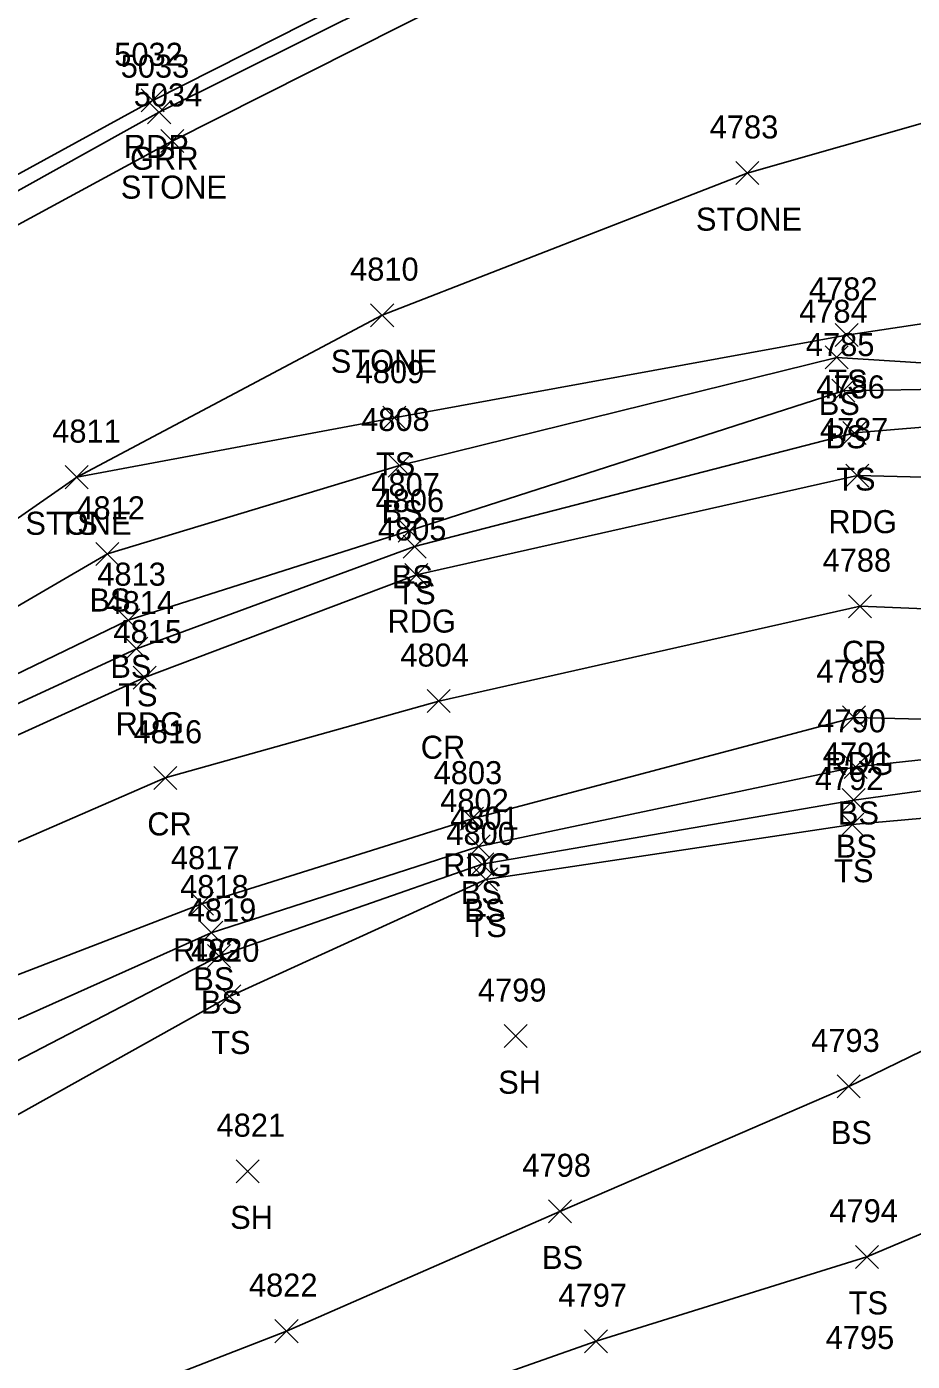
# Model space of a CAD drawing. Extents: x 1505656 to 1508446, y 700805 to 703031.
# Drawn here: x 1506352.2 to 1506429, y 701620.6 to 701736.4 of the extents above; entities that cross this region are included whole.
import ezdxf

# ---------------------------------------------------------------- set-up
doc = ezdxf.new("R2010")
doc.units = 0
for name, color, linetype in [('L_A', 7, 'Continuous'), ('L_I', 7, 'Continuous'), ('L_TIC', 7, 'Continuous'), ('LASF', 7, 'Continuous'), ('LELB', 7, 'Continuous'), ('P_A', 7, 'Continuous'), ('P_I', 7, 'Continuous'), ('P_TIC', 7, 'Continuous'), ('PET', 7, 'Continuous'), ('PEU', 7, 'Continuous'), ('PRC', 7, 'Continuous'), ('R_A', 7, 'Continuous'), ('R_I', 7, 'Continuous'), ('R_TIC', 7, 'Continuous'), ('RGR', 7, 'Continuous')]:
    doc.layers.add(name, color=color, linetype=linetype)

msp = doc.modelspace()

# ---------------------------------------------------------------- linework, layer by layer
at = {"layer": 'L_TIC'}
for points in [[(1506363.79, 701725.48), (1506365.79, 701727.48)], [(1506365.79, 701725.48), (1506363.79, 701727.48)], [(1506413.7, 701722.7), (1506415.7, 701724.7)], [(1506415.7, 701722.7), (1506413.7, 701724.7)], [(1506382.01, 701710.36), (1506384.01, 701712.36)], [(1506384.01, 701710.36), (1506382.01, 701712.36)], [(1506422.31, 701708.64), (1506424.31, 701710.64)], [(1506424.31, 701708.64), (1506422.31, 701710.64)], [(1506421.46, 701706.7), (1506423.46, 701708.7)], [(1506423.46, 701706.7), (1506421.46, 701708.7)], [(1506422.04, 701703.81), (1506424.04, 701705.81)], [(1506424.04, 701703.81), (1506422.04, 701705.81)], [(1506383.06, 701701.46), (1506385.06, 701703.46)], [(1506385.06, 701701.46), (1506383.06, 701703.46)], [(1506423, 701700.14), (1506425, 701702.14)], [(1506425, 701700.14), (1506423, 701702.14)], [(1506383.52, 701697.31), (1506385.52, 701699.31)], [(1506385.52, 701697.31), (1506383.52, 701699.31)], [(1506355.51, 701696.3), (1506357.51, 701698.3)], [(1506357.51, 701696.3), (1506355.51, 701698.3)], [(1506355.51, 701696.3), (1506357.51, 701698.3)], [(1506357.51, 701696.3), (1506355.51, 701698.3)], [(1506384.41, 701691.66), (1506386.41, 701693.66)], [(1506386.41, 701691.66), (1506384.41, 701693.66)], [(1506384.83, 701690.27), (1506386.83, 701692.27)], [(1506386.83, 701690.27), (1506384.83, 701692.27)], [(1506358.17, 701689.64), (1506360.17, 701691.64)], [(1506360.17, 701689.64), (1506358.17, 701691.64)], [(1506359.98, 701683.88), (1506361.98, 701685.88)], [(1506361.98, 701683.88), (1506359.98, 701685.88)], [(1506360.69, 701681.41), (1506362.69, 701683.41)], [(1506362.69, 701681.41), (1506360.69, 701683.41)], [(1506423.11, 701671.15), (1506425.11, 701673.15)], [(1506425.11, 701671.15), (1506423.11, 701673.15)], [(1506422.94, 701668.27), (1506424.94, 701670.27)], [(1506424.94, 701668.27), (1506422.94, 701670.27)], [(1506422.82, 701666.14), (1506424.82, 701668.14)], [(1506424.82, 701666.14), (1506422.82, 701668.14)], [(1506390.39, 701664.24), (1506392.39, 701666.24)], [(1506392.39, 701664.24), (1506390.39, 701666.24)], [(1506390.69, 701662.7), (1506392.69, 701664.7)], [(1506392.69, 701662.7), (1506390.69, 701664.7)], [(1506391.01, 701661.38), (1506393.01, 701663.38)], [(1506393.01, 701661.38), (1506391.01, 701663.38)], [(1506367.18, 701656.76), (1506369.18, 701658.76)], [(1506369.18, 701656.76), (1506367.18, 701658.76)], [(1506367.84, 701654.73), (1506369.84, 701656.73)], [(1506369.84, 701654.73), (1506367.84, 701656.73)], [(1506368.76, 701651.23), (1506370.76, 701653.23)], [(1506370.76, 701651.23), (1506368.76, 701653.23)], [(1506393.59, 701647.78), (1506395.59, 701649.78)], [(1506395.59, 701647.78), (1506393.59, 701649.78)], [(1506422.5, 701643.41), (1506424.5, 701645.41)], [(1506424.5, 701643.41), (1506422.5, 701645.41)], [(1506370.34, 701636.05), (1506372.34, 701638.05)], [(1506372.34, 701636.05), (1506370.34, 701638.05)], [(1506397.44, 701632.57), (1506399.44, 701634.57)], [(1506399.44, 701632.57), (1506397.44, 701634.57)], [(1506424.08, 701628.62), (1506426.08, 701630.62)], [(1506426.08, 701628.62), (1506424.08, 701630.62)], [(1506373.71, 701622.17), (1506375.71, 701624.17)], [(1506375.71, 701622.17), (1506373.71, 701624.17)], [(1506400.57, 701621.29), (1506402.57, 701623.29)], [(1506402.57, 701621.29), (1506400.57, 701623.29)]]:
    msp.add_lwpolyline(points, dxfattribs=at)
at = {"layer": 'LASF'}
msp.add_lwpolyline([(1506429.68, 701752.83), (1506443.79, 701749.58), (1506462.7, 701738.25), (1506448, 701734.79), (1506439.12, 701730.66), (1506414.7, 701723.7), (1506383.01, 701711.36), (1506356.51, 701697.3), (1506322.23, 701673.42), (1506294.03, 701680.48), (1506288.73, 701684.49), (1506312.05, 701697.87), (1506364.79, 701726.48), (1506396.56, 701742.51), (1506417.45, 701749.86)], dxfattribs=at)
at = {"layer": 'LELB'}
for points in [[(1506444.2, 701712.77), (1506423.31, 701709.64), (1506384.06, 701702.46), (1506356.51, 701697.3)], [(1506439.67, 701705.09), (1506439.84, 701706.59), (1506422.46, 701707.7), (1506384.52, 701698.31), (1506359.17, 701690.64), (1506320.25, 701667.95), (1506278.54, 701648.54), (1506245.9, 701631.84)], [(1506439.67, 701705.09), (1506423.04, 701704.81), (1506385.41, 701692.66), (1506360.98, 701684.88), (1506321.19, 701665.64), (1506279.84, 701646.54), (1506249.51, 701629.08), (1506209.1, 701611.11), (1506171.89, 701595.41), (1506131.01, 701577.86), (1506104.62, 701564.81), (1506102.86, 701567.32), (1506129.39, 701579.69), (1506163.08, 701601.74)], [(1506443.16, 701702.73), (1506424, 701701.14), (1506385.83, 701691.27), (1506361.69, 701682.41), (1506322.45, 701664.3), (1506280.69, 701644.91), (1506249.51, 701629.08)], [(1506509.21, 701611.03), (1506507.44, 701618.38), (1506501.19, 701629.63), (1506493.28, 701641.73), (1506487.58, 701650), (1506474.34, 701662.65), (1506459.98, 701669.04), (1506440.83, 701673.95), (1506424.11, 701672.15), (1506391.39, 701665.24), (1506368.18, 701657.76), (1506332.08, 701641.61), (1506290.37, 701623.5), (1506260.15, 701608.32), (1506217.93, 701589.2), (1506179.42, 701572.42), (1506142.47, 701555.66), (1506111.55, 701540.68), (1506083.73, 701530.64), (1506052.54, 701524.58), (1506019.1, 701514.86), (1506001, 701512.92)], [(1506505.93, 701609.05), (1506503.05, 701618.08), (1506498.28, 701627.09), (1506492.11, 701640.81), (1506486.47, 701649.13), (1506473.24, 701661.34), (1506459.24, 701667.42), (1506439.7, 701671.42), (1506423.94, 701669.27), (1506391.69, 701663.7), (1506368.84, 701655.73), (1506334.29, 701637.81), (1506294.64, 701613.24), (1506262.7, 701600.99), (1506219.1, 701587.01), (1506179.81, 701571.09), (1506142.47, 701555.66)], [(1506501.04, 701604.88), (1506496.49, 701618.92), (1506488.49, 701638.33), (1506484.16, 701646.68), (1506470.49, 701657.41), (1506458.02, 701664.05), (1506439.08, 701668.51), (1506423.82, 701667.14), (1506392.01, 701662.38), (1506369.76, 701652.23), (1506335.43, 701633.06), (1506298.71, 701603.99)], [(1506477.45, 701634.17), (1506465.86, 701646.11), (1506449.94, 701651.79), (1506436.18, 701650.58), (1506423.5, 701644.41), (1506398.44, 701633.57), (1506374.71, 701623.17), (1506339.34, 701609.43), (1506298.71, 701603.99), (1506265.2, 701595.37), (1506220.27, 701580.75), (1506181.48, 701566.74)], [(1506464.89, 701630.33), (1506459.78, 701641.23), (1506438.81, 701635.44), (1506425.08, 701629.62), (1506401.57, 701622.29), (1506377.12, 701613.69), (1506342.27, 701601.76), (1506302.18, 701594.41), (1506270.03, 701583.3), (1506223.11, 701570.14), (1506184.48, 701557.95), (1506143.89, 701547.39), (1506113.07, 701537.26)]]:
    msp.add_lwpolyline(points, dxfattribs=at)
at = {"layer": 'P_TIC'}
for points in [[(1506362.1, 701729.01), (1506364.1, 701731.01)], [(1506364.1, 701729.01), (1506362.1, 701731.01)], [(1506423.25, 701696.44), (1506425.25, 701698.44)], [(1506425.25, 701696.44), (1506423.25, 701698.44)], [(1506384.98, 701687.81), (1506386.98, 701689.81)], [(1506386.98, 701687.81), (1506384.98, 701689.81)], [(1506423.49, 701685.1), (1506425.49, 701687.1)], [(1506425.49, 701685.1), (1506423.49, 701687.1)], [(1506361.39, 701678.9), (1506363.39, 701680.9)], [(1506363.39, 701678.9), (1506361.39, 701680.9)], [(1506386.92, 701676.86), (1506388.92, 701678.86)], [(1506388.92, 701676.86), (1506386.92, 701678.86)], [(1506422.96, 701675.45), (1506424.96, 701677.45)], [(1506424.96, 701675.45), (1506422.96, 701677.45)], [(1506363.19, 701670.2), (1506365.19, 701672.2)], [(1506365.19, 701670.2), (1506363.19, 701672.2)], [(1506389.82, 701666.65), (1506391.82, 701668.65)], [(1506391.82, 701666.65), (1506389.82, 701668.65)], [(1506366.37, 701659.27), (1506368.37, 701661.27)], [(1506368.37, 701659.27), (1506366.37, 701661.27)]]:
    msp.add_lwpolyline(points, dxfattribs=at)
at = {"layer": 'PET'}
msp.add_lwpolyline([(1505992.82, 701526.62), (1506019.68, 701536.96), (1506041.12, 701547.38), (1506078.94, 701568.61), (1506107.14, 701585.72), (1506155.42, 701613.4), (1506197.61, 701637.13), (1506235.98, 701659.24), (1506270.79, 701679.06), (1506309.7, 701700.77), (1506363.1, 701730.01), (1506394.98, 701746.14), (1506415.62, 701755.89), (1506435.04, 701763.8), (1506427.31, 701775.57), (1506419.65, 701788)], dxfattribs=at)
at = {"layer": 'PEU'}
for points in [[(1506525.78, 701615.67), (1506519.5, 701633.43), (1506513.15, 701649.3), (1506503.08, 701665.91), (1506489.52, 701679.31), (1506470.51, 701690.89), (1506460.49, 701693.33), (1506439.12, 701697.08), (1506424.25, 701697.44), (1506385.98, 701688.81), (1506362.39, 701679.9), (1506323.43, 701662.22), (1506281.23, 701643.19), (1506252.35, 701627.76), (1506209.85, 701609.53), (1506173.44, 701590.33), (1506132.93, 701573.39), (1506105.98, 701559.11), (1506089.21, 701557.37), (1506082.67, 701561.4), (1506078.94, 701568.61)], [(1506512.36, 701612.05), (1506509.58, 701619.24), (1506503.6, 701631.14), (1506495.87, 701643.5), (1506490.15, 701651.91), (1506475.68, 701664.25), (1506461.93, 701671.49), (1506441.69, 701676.01), (1506423.96, 701676.45), (1506390.82, 701667.65), (1506367.37, 701660.27), (1506329.82, 701645.8), (1506288.78, 701627.12), (1506258.45, 701612.59), (1506216.06, 701594.6), (1506177.68, 701577.39), (1506139.98, 701558.64), (1506110.2, 701544.77), (1506096.87, 701538.26), (1506082.45, 701533.62), (1506051.95, 701526.91), (1506019.21, 701522.3), (1505992.82, 701526.62)]]:
    msp.add_lwpolyline(points, dxfattribs=at)
at = {"layer": 'PRC'}
msp.add_lwpolyline([(1506519.07, 701614.01), (1506506.17, 701642.82), (1506497.05, 701654.53), (1506481.68, 701671.51), (1506464.91, 701680.72), (1506446.99, 701685.19), (1506424.49, 701686.1), (1506387.92, 701677.86), (1506364.19, 701671.2), (1506326.34, 701654.75), (1506285.02, 701635.25), (1506254.86, 701621.58), (1506213.39, 701600.27), (1506174.81, 701583.72), (1506136.29, 701565.39), (1506108.2, 701552.45), (1506085.49, 701543.92), (1506066.01, 701541.94)], dxfattribs=at)
at = {"layer": 'R_TIC'}
for points in [[(1506362.66, 701727.98), (1506364.66, 701729.98)], [(1506364.66, 701727.98), (1506362.66, 701729.98)]]:
    msp.add_lwpolyline(points, dxfattribs=at)
at = {"layer": 'RGR'}
msp.add_lwpolyline([(1506085.73, 701568.29), (1506107.54, 701584.72), (1506155.8, 701612.35), (1506198.2, 701636.56), (1506236.66, 701658.36), (1506270.99, 701677.92), (1506310.51, 701699.4), (1506363.66, 701728.98), (1506395.74, 701744.99), (1506415.68, 701754.26), (1506427.01, 701758.86)], dxfattribs=at)

# ---------------------------------------------------------------- texts
at = {"layer": 'L_A'}
for s, p in [('STONE', (1506360.33, 701721.48)), ('STONE', (1506410.24, 701718.7)), ('STONE', (1506378.55, 701706.36)), ('TS', (1506421.72, 701704.64)), ('BS', (1506420.9, 701702.7)), ('BS', (1506421.48, 701699.81)), ('TS', (1506382.47, 701697.46)), ('TS', (1506422.41, 701696.14)), ('STONE', (1506352.05, 701692.3)), ('TS', (1506354.92, 701692.3)), ('BS', (1506382.96, 701693.31)), ('BS', (1506383.85, 701687.66)), ('BS', (1506357.61, 701685.64)), ('TS', (1506384.24, 701686.27)), ('BS', (1506359.42, 701679.88)), ('TS', (1506360.1, 701677.41)), ('BS', (1506422.56, 701667.15)), ('BS', (1506422.38, 701664.27)), ('TS', (1506422.23, 701662.14)), ('BS', (1506389.83, 701660.24)), ('BS', (1506390.13, 701658.7)), ('TS', (1506390.42, 701657.38)), ('BS', (1506366.62, 701652.76)), ('BS', (1506367.28, 701650.73)), ('TS', (1506368.17, 701647.23)), ('SH', (1506393.08, 701643.78)), ('BS', (1506421.94, 701639.41)), ('SH', (1506369.82, 701632.05)), ('BS', (1506396.88, 701628.57)), ('TS', (1506423.49, 701624.62))]:
    msp.add_text(s, height=2, dxfattribs=at).set_placement(p)
at = {"layer": 'L_I'}
for s, p in [('5034', (1506361.45, 701729.48)), ('4783', (1506411.44, 701726.7)), ('4810', (1506380.23, 701714.36)), ('4782', (1506420.05, 701712.64)), ('4784', (1506419.2, 701710.7)), ('4785', (1506419.78, 701707.81)), ('4809', (1506380.71, 701705.46)), ('4786', (1506420.69, 701704.14)), ('4811', (1506354.38, 701700.3)), ('4811', (1506354.38, 701700.3)), ('4808', (1506381.18, 701701.31)), ('4807', (1506382.07, 701695.66)), ('4812', (1506356.47, 701693.64)), ('4806', (1506382.44, 701694.27)), ('4813', (1506358.29, 701687.88)), ('4814', (1506359, 701685.41)), ('4790', (1506420.77, 701675.15)), ('4791', (1506421.25, 701672.27)), ('4792', (1506420.56, 701670.14)), ('4802', (1506388.05, 701668.24)), ('4801', (1506388.92, 701666.7)), ('4800', (1506388.58, 701665.38)), ('4818', (1506365.48, 701660.76)), ('4819', (1506366.14, 701658.73)), ('4820', (1506366.41, 701655.23)), ('4799', (1506391.32, 701651.78)), ('4793', (1506420.24, 701647.41)), ('4821', (1506368.64, 701640.05)), ('4798', (1506395.18, 701636.57)), ('4794', (1506421.82, 701632.62)), ('4822', (1506371.45, 701626.17)), ('4797', (1506398.31, 701625.29)), ('4795', (1506421.5, 701621.62))]:
    msp.add_text(s, height=2, dxfattribs=at).set_placement(p)
at = {"layer": 'P_A'}
for s, p in [('RDP', (1506360.59, 701725.01)), ('RDG', (1506421.73, 701692.44)), ('RDG', (1506383.47, 701683.81)), ('CR', (1506422.92, 701681.1)), ('RDG', (1506359.88, 701674.9)), ('CR', (1506386.36, 701672.86)), ('RDG', (1506421.45, 701671.45)), ('CR', (1506362.63, 701666.2)), ('RDG', (1506388.31, 701662.65)), ('RDG', (1506364.86, 701655.27))]:
    msp.add_text(s, height=2, dxfattribs=at).set_placement(p)
at = {"layer": 'P_I'}
for s, p in [('5032', (1506359.76, 701733.01)), ('4787', (1506420.99, 701700.44)), ('4805', (1506382.64, 701691.81)), ('4788', (1506421.23, 701689.1)), ('4815', (1506359.69, 701682.9)), ('4804', (1506384.59, 701680.86)), ('4789', (1506420.7, 701679.45)), ('4816', (1506361.44, 701674.2)), ('4803', (1506387.48, 701670.65)), ('4817', (1506364.68, 701663.27))]:
    msp.add_text(s, height=2, dxfattribs=at).set_placement(p)
at = {"layer": 'R_A'}
msp.add_text('GRR', height=2, dxfattribs=at).set_placement((1506361.14, 701723.98))
at = {"layer": 'R_I'}
msp.add_text('5033', height=2, dxfattribs=at).set_placement((1506360.32, 701731.98))

doc.saveas('drawing.dxf')
